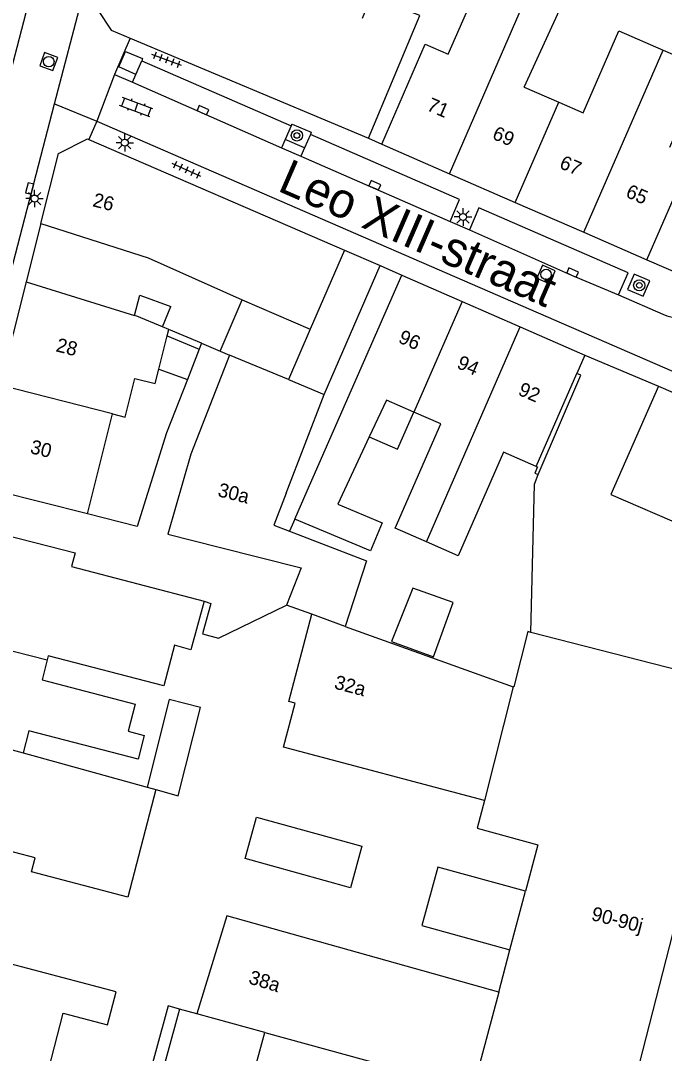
# Model space of a CAD drawing. Extents: x 132998 to 136004, y 396998 to 398512.
# Drawn here: x 133609.4 to 133655.4, y 397867.7 to 397941.4 of the extents above; entities that cross this region are included whole.
import ezdxf

# ---------------------------------------------------------------- set-up
doc = ezdxf.new("R2010")
doc.units = 0
for name, color, linetype in [('gg-afsc-erfafscheiding', 7, 'Continuous'), ('gg-afsc-hekwerk', 7, 'Continuous'), ('gg-afsc-muur', 7, 'Continuous'), ('gg-anno-huisnummerreeks BGT', 7, 'Continuous'), ('gg-anno-openbare ruimte label', 7, 'Continuous'), ('gg-bbg-bijgebouw', 7, 'Continuous'), ('gg-bbg-gedigitaliseerde bebouwing', 7, 'Continuous'), ('gg-bbg-gedigitaliseerde bijgebouw', 7, 'Continuous'), ('gg-bbg-hoofdgebouw', 7, 'Continuous'), ('gg-bbg-luifel en loopbrug', 7, 'Continuous'), ('gg-bbg-tussenscheiding', 7, 'Continuous'), ('gg-knt-verharding', 7, 'Continuous'), ('gg-knt-verharding nz', 7, 'Continuous'), ('gt-grn-weggrens', 7, 'Continuous'), ('gt-symb-boom', 7, 'Continuous'), ('gt-symb-klinker verharding', 7, 'Continuous'), ('gt-symb-kolk', 7, 'Continuous'), ('gt-symb-lichtmast', 7, 'Continuous'), ('gt-symb-rioolschacht', 7, 'Continuous'), ('gt-symb-tegel verharding', 7, 'Continuous')]:
    doc.layers.add(name, color=color, linetype=linetype)

# ---------------------------------------------------------------- blocks, each defined once
blk = doc.blocks.new('gt0-BOOM')
at = {"layer": 'gt-symb-boom'}
for radius in [0.4, 0.2]:
    blk.add_circle((0, 0), radius, dxfattribs=at)
blk = doc.blocks.new('gt0-KOLK')
at = {"layer": 'gt-symb-kolk'}
blk.add_lwpolyline([(0, 0), (0.375, 0), (0.375, 0.4), (-0.375, 0.4), (-0.375, 0), (0, 0)], dxfattribs=at)
blk = doc.blocks.new('gt0-RS')
at = {"layer": 'gt-symb-rioolschacht'}
blk.add_lwpolyline([(-0.5, -0.5), (0.5, -0.5), (0.5, 0.5), (-0.5, 0.5)], close=True, dxfattribs=at)
blk.add_circle((0, 0), 0.375, dxfattribs=at)
blk = doc.blocks.new('gt0-LMAST')
at = {"layer": 'gt-symb-lichtmast'}
for p, q in [((-0.182, 0.173), (-0.447, 0.438)), ((-0.005, 0.246), (-0.005, 0.621)), ((0.172, 0.173), (0.437, 0.438)), ((-0.255, -0.004), (-0.63, -0.004)), ((-0.182, -0.181), (-0.447, -0.446)), ((-0.005, -0.254), (-0.005, -0.629)), ((0.437, -0.446), (0.172, -0.181)), ((0.245, -0.004), (0.62, -0.004))]:
    blk.add_line(p, q, dxfattribs=at)
blk.add_circle((-0.005, -0.004), 0.25, dxfattribs=at)
blk = doc.blocks.new('gt0-KL1')
at = {"layer": 'gt-symb-klinker verharding'}
for p, q in [((-1.15, 0.3), (1.15, 0.3)), ((-1, -0.3), (-1, 0.3)), ((-0.5, 0.3), (-0.5, 0.45)), ((0, -0.3), (0, 0.3)), ((0.5, 0.3), (0.5, 0.45)), ((1, -0.3), (1, 0.3)), ((-1.15, -0.3), (1.15, -0.3)), ((-0.5, -0.45), (-0.5, -0.3)), ((0.5, -0.45), (0.5, -0.3))]:
    blk.add_line(p, q, dxfattribs=at)
blk = doc.blocks.new('gt0-TEG1')
at = {"layer": 'gt-symb-tegel verharding'}
for p, q in [((-1.125, 0), (1.125, 0)), ((-0.9, -0.25), (-0.9, 0.25)), ((-0.45, -0.25), (-0.45, 0.25)), ((0, -0.25), (0, 0.25)), ((0.45, -0.25), (0.45, 0.25)), ((0.9, -0.25), (0.9, 0.25))]:
    blk.add_line(p, q, dxfattribs=at)

msp = doc.modelspace()

# ---------------------------------------------------------------- linework, layer by layer
at = {"layer": 'gg-afsc-erfafscheiding'}
for p, q in [((133622.354, 397918.414), (133622.191, 397917.995)), ((133623.686, 397917.857), (133624.365, 397917.573)), ((133629.024, 397905.871), (133628.642, 397905))]:
    msp.add_line(p, q, dxfattribs=at)
for points in [[(133621.345, 397915.826), (133619.858, 397912.009), (133617.771, 397905.345), (133614.203, 397906.24)], [(133622.546, 397900.013), (133623.026, 397899.834), (133622.437, 397897.675), (133623.571, 397897.361), (133628.432, 397899.721)], [(133620.775, 397870.887), (133619.963, 397871.138), (133616.361, 397857.914), (133609.664, 397859.687)]]:
    msp.add_lwpolyline(points, dxfattribs=at)
at = {"layer": 'gg-afsc-hekwerk'}
msp.add_line((133649.72, 397917.56), (133654.98, 397915.36), dxfattribs=at)
at = {"layer": 'gg-afsc-muur'}
for points in [[(133646.38, 397909.052), (133649.442, 397916.135), (133649.152, 397916.259)], [(133646.253, 397909.622), (133646.34, 397909.584), (133646.155, 397909.147), (133646.38, 397909.052)], [(133645.874, 397897.783), (133646.13, 397908.348), (133646.38, 397909.052)]]:
    msp.add_lwpolyline(points, dxfattribs=at)
at = {"layer": 'gg-bbg-bijgebouw'}
for p, q in [((133610.883, 397926.954), (133609.828, 397922.788)), ((133632.553, 397925.06), (133635.12, 397923.95))]:
    msp.add_line(p, q, dxfattribs=at)
at = {"layer": 'gg-bbg-gedigitaliseerde bebouwing'}
for p, q in [((133645.392, 397936.687), (133647.869, 397935.612)), ((133625.253, 397921.522), (133630.119, 397919.412)), ((133619.901, 397918.952), (133620.012, 397919.394)), ((133619.3, 397916.559), (133619.901, 397918.952)), ((133628.569, 397915.816), (133624.365, 397917.573)), ((133646.253, 397909.622), (133649.152, 397916.259)), ((133628.397, 397907.719), (133631.119, 397914.75)), ((133614.203, 397906.24), (133615.993, 397913.379)), ((133634.322, 397911.728), (133632.078, 397906.932)), ((133613.077, 397902.474), (133622.546, 397900.013)), ((133630.241, 397899.069), (133628.432, 397899.721)), ((133632.623, 397898.212), (133644.614, 397893.896)), ((133609.613, 397889.177), (133618.479, 397886.737)), ((133618.479, 397886.737), (133619.094, 397886.568)), ((133643.574, 397872.118), (133644.379, 397875.127)), ((133626.867, 397869.227), (133641.72, 397865.179))]:
    msp.add_line(p, q, dxfattribs=at)
for points in [[(133645.392, 397936.687), (133649.627, 397945.931), (133647.227, 397946.976)], [(133639.975, 397939.042), (133642.837, 397945.615), (133643.665, 397945.255)], [(133634.27, 397933.04), (133637.934, 397941.791), (133634.462, 397943.168), (133633.837, 397941.591)], [(133647.869, 397935.612), (133649.608, 397934.857), (133652.148, 397940.71), (133655.318, 397939.334)], [(133635.22, 397932.62), (133638.327, 397939.76), (133639.975, 397939.042)], [(133655.318, 397939.334), (133658.235, 397938.068), (133655.77, 397932.389)], [(133629.024, 397905.871), (133629.906, 397907.881), (133636.66, 397923.27)], [(133619.559, 397919.583), (133617.741, 397920.343), (133617.582, 397920.392)], [(133624.365, 397917.573), (133621.595, 397910.505), (133619.939, 397904.784), (133623.623, 397903.856)], [(133615.993, 397913.379), (133616.91, 397913.145), (133617.603, 397915.906), (133619.045, 397915.544), (133619.3, 397916.559)], [(133637.506, 397913.505), (133635.553, 397914.359), (133634.322, 397911.728)], [(133638.409, 397904.237), (133636.192, 397905.206), (133639.449, 397912.656), (133637.506, 397913.505)], [(133646.253, 397909.622), (133643.917, 397910.643), (133640.682, 397903.243), (133638.409, 397904.237)], [(133628.397, 397907.719), (133627.513, 397905.437), (133628.642, 397905)], [(133632.078, 397906.932), (133635.265, 397905.595), (133634.429, 397903.603), (133629.024, 397905.871)], [(133628.642, 397905), (133634.124, 397902.876), (133632.623, 397898.212)], [(133623.623, 397903.856), (133629.463, 397902.385), (133628.432, 397899.721)], [(133622.546, 397900.013), (133621.582, 397896.541), (133620.426, 397896.862)], [(133642.553, 397885.782), (133628.212, 397889.589), (133629.043, 397892.72), (133628.588, 397892.841), (133630.241, 397899.069)], [(133645.663, 397897.838), (133644.644, 397893.885), (133644.614, 397893.896)], [(133620.426, 397896.862), (133619.671, 397893.962), (133611.417, 397896.11), (133611.343, 397895.828)], [(133611.343, 397895.828), (133610.969, 397894.389), (133617.614, 397892.66), (133617.11, 397890.724), (133618.272, 397890.422), (133617.831, 397888.729), (133610.025, 397890.759), (133609.613, 397889.177)], [(133619.094, 397886.568), (133617.097, 397878.893), (133610.213, 397880.684), (133610.476, 397881.693), (133607.56, 397882.449)], [(133642.553, 397885.782), (133642.044, 397883.807), (133646.379, 397882.611), (133645.496, 397879.306)], [(133643.574, 397872.118), (133624.173, 397877.563), (133622.016, 397870.549)], [(133613.879, 397862.863), (133614.023, 397863.421), (133610.828, 397864.244), (133612.466, 397870.606), (133615.652, 397869.786), (133616.253, 397872.119), (133598.59, 397876.79)]]:
    msp.add_lwpolyline(points, dxfattribs=at)
at = {"layer": 'gg-bbg-gedigitaliseerde bijgebouw'}
for p, q in [((133631.119, 397914.75), (133635.12, 397923.95)), ((133623.686, 397917.857), (133625.253, 397921.522)), ((133619.559, 397919.583), (133620.176, 397921.028)), ((133622.354, 397918.414), (133620.012, 397919.394)), ((133630.119, 397919.412), (133628.569, 397915.816)), ((133622.354, 397918.414), (133623.686, 397917.857)), ((133622.016, 397870.549), (133620.775, 397870.887))]:
    msp.add_line(p, q, dxfattribs=at)
for points in [[(133617.582, 397920.392), (133617.948, 397921.838), (133620.176, 397921.028)], [(133637.448, 397900.937), (133635.931, 397897.128), (133638.928, 397896.047), (133640.319, 397899.902), (133637.448, 397900.937)], [(133625.47, 397881.633), (133626.283, 397884.591), (133633.81, 397882.52), (133632.996, 397879.563), (133625.47, 397881.633)], [(133645.496, 397879.306), (133639.237, 397881.028), (133638.091, 397876.859), (133644.379, 397875.127)], [(133620.775, 397870.887), (133618.005, 397860.719), (133624.098, 397859.059), (133626.867, 397869.227)]]:
    msp.add_lwpolyline(points, dxfattribs=at)
at = {"layer": 'gg-bbg-hoofdgebouw'}
for p, q in [((133617.261, 397940.192), (133634.27, 397933.04)), ((133614.31, 397932.951), (133632.553, 397925.06)), ((133635.22, 397932.62), (133640.06, 397930.513)), ((133640.06, 397930.513), (133644.759, 397928.467)), ((133644.759, 397928.467), (133649.658, 397926.334)), ((133649.658, 397926.334), (133654.153, 397924.377)), ((133654.153, 397924.377), (133658.51, 397922.48)), ((133636.66, 397923.27), (133640.954, 397921.393)), ((133609.828, 397922.788), (133607.964, 397915.424)), ((133640.954, 397921.393), (133645.114, 397919.574)), ((133645.114, 397919.574), (133649.72, 397917.56)), ((133649.72, 397917.56), (133649.152, 397916.259)), ((133654.98, 397915.36), (133666.672, 397910.299)), ((133614.203, 397906.24), (133606.15, 397908.26)), ((133645.874, 397897.783), (133645.663, 397897.838))]:
    msp.add_line(p, q, dxfattribs=at)
for points in [[(133615.18, 397945.542), (133614.94, 397942.24), (133615.91, 397940.76), (133617.261, 397940.192)], [(133610.883, 397926.954), (133612.15, 397931.96), (133614.22, 397932.99), (133614.31, 397932.951)], [(133654.98, 397915.36), (133651.582, 397907.615), (133662.39, 397902.955)], [(133605.41, 397905.47), (133613.327, 397903.453), (133613.077, 397902.474)], [(133656.898, 397860.803), (133655.779, 397861.086), (133654.993, 397857.74), (133651.477, 397858.645), (133660.53, 397893.898), (133660.426, 397893.929), (133660.451, 397894.026), (133645.874, 397897.783)]]:
    msp.add_lwpolyline(points, dxfattribs=at)
at = {"layer": 'gg-bbg-luifel en loopbrug'}
for p, q in [((133619.901, 397918.952), (133622.191, 397917.995)), ((133622.191, 397917.995), (133621.345, 397915.826)), ((133619.3, 397916.559), (133621.345, 397915.826))]:
    msp.add_line(p, q, dxfattribs=at)
for points in [[(133634.322, 397911.728), (133636.343, 397910.845), (133637.506, 397913.505)], [(133619.094, 397886.568), (133620.697, 397886.127), (133622.287, 397892.43), (133620.057, 397892.992), (133618.479, 397886.737)]]:
    msp.add_lwpolyline(points, dxfattribs=at)
at = {"layer": 'gg-bbg-tussenscheiding'}
for p, q in [((133640.06, 397930.513), (133645.521, 397943.057)), ((133649.658, 397926.334), (133655.318, 397939.334)), ((133644.759, 397928.467), (133647.869, 397935.612)), ((133654.153, 397924.377), (133657.232, 397931.449)), ((133632.553, 397925.06), (133630.119, 397919.412)), ((133609.828, 397922.788), (133617.582, 397920.392)), ((133640.954, 397921.393), (133637.506, 397913.505)), ((133620.012, 397919.394), (133619.559, 397919.583)), ((133638.409, 397904.237), (133645.114, 397919.574)), ((133628.569, 397915.816), (133631.119, 397914.75)), ((133615.993, 397913.379), (133607.964, 397915.424)), ((133632.623, 397898.212), (133630.241, 397899.069)), ((133603.422, 397897.828), (133611.343, 397895.828)), ((133644.614, 397893.896), (133642.553, 397885.782)), ((133601.735, 397891.343), (133609.613, 397889.177)), ((133644.379, 397875.127), (133645.496, 397879.306)), ((133643.574, 397872.118), (133641.72, 397865.179)), ((133626.867, 397869.227), (133622.016, 397870.549))]:
    msp.add_line(p, q, dxfattribs=at)
msp.add_lwpolyline([(133610.883, 397926.954), (133618.535, 397924.516), (133625.253, 397921.522)], dxfattribs=at)
at = {"layer": 'gg-knt-verharding'}
for p, q in [((133617.261, 397940.192), (133616.135, 397937.59)), ((133617.673, 397937.594), (133618.101, 397938.57)), ((133618.101, 397938.57), (133628.755, 397933.921)), ((133616.135, 397937.59), (133617.428, 397937.034)), ((133617.428, 397937.034), (133617.673, 397937.594)), ((133614.874, 397934.262), (133614.31, 397932.951)), ((133614.874, 397934.262), (133704.097, 397895.507)), ((133628.755, 397933.921), (133628.331, 397932.961)), ((133630.132, 397933.315), (133629.716, 397932.357)), ((133628.331, 397932.961), (133628.066, 397932.362)), ((133629.716, 397932.357), (133628.331, 397932.961)), ((133634.27, 397933.04), (133635.22, 397932.62)), ((133628.066, 397932.362), (133629.453, 397931.752)), ((133629.716, 397932.357), (133629.453, 397931.752)), ((133640.102, 397927.103), (133641.495, 397926.501)), ((133635.12, 397923.95), (133636.66, 397923.27)), ((133652.125, 397921.873), (133655.298, 397920.494))]:
    msp.add_line(p, q, dxfattribs=at)
for points in [[(133611.866, 397935.493), (133613.875, 397943.22), (133618.023, 398000)], [(133565.5, 397779.742), (133577.243, 397816.67), (133610.301, 397943.866), (133613.733, 397990.772)], [(133617.673, 397937.594), (133616.45, 397938.147), (133616.924, 397939.238), (133618.14, 397938.724), (133618.101, 397938.57)], [(133571.202, 397785.807), (133580.793, 397815.951), (133611.866, 397935.493)], [(133628.755, 397933.921), (133628.839, 397934.057), (133630.178, 397933.475), (133630.132, 397933.315)], [(133640.102, 397927.103), (133640.781, 397928.675), (133630.132, 397933.315)], [(133652.125, 397921.873), (133652.806, 397923.431), (133642.164, 397928.074), (133641.495, 397926.501)], [(133654.357, 397922.871), (133653.255, 397923.345), (133652.769, 397922.256), (133653.889, 397921.771), (133654.357, 397922.871)]]:
    msp.add_lwpolyline(points, dxfattribs=at)
msp.add_arc((133656.592, 397923.334), 3.121, 245.50088, 331.7088, dxfattribs=at)
at = {"layer": 'gg-knt-verharding nz'}
for p, q in [((133617.428, 397937.034), (133628.066, 397932.362)), ((133629.453, 397931.752), (133640.102, 397927.103))]:
    msp.add_line(p, q, dxfattribs=at)
msp.add_lwpolyline([(133641.495, 397926.501), (133648.77, 397923.282), (133652.125, 397921.873)], dxfattribs=at)
at = {"layer": 'gt-grn-weggrens'}
for p in [(133616.135, 397937.59), (133611.866, 397935.493)]:
    msp.add_line(p, (133614.874, 397934.262), dxfattribs=at)

# ---------------------------------------------------------------- block references
at = {"layer": 'gt-symb-boom'}
for p in [(133629.163, 397933.241), (133653.609, 397922.546)]:
    msp.add_blockref('gt0-BOOM', p, dxfattribs=at)
at = {"layer": 'gt-symb-klinker verharding', "rotation": 159.39030706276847}
msp.add_blockref('gt0-KL1', (133617.689, 397935.26), dxfattribs=at)
at = {"layer": 'gt-symb-kolk'}
for p, rotation in [((133622.377, 397934.861), -23.694971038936), ((133610.278, 397929.406), 75.40804379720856), ((133634.647, 397929.508), -23.386642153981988), ((133648.769, 397923.282), -23.89847786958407)]:
    msp.add_blockref('gt0-KOLK', p, dxfattribs=dict(at, rotation=rotation))
at = {"layer": 'gt-symb-lichtmast'}
for p in [(133616.883, 397932.728), (133610.438, 397928.743), (133641.033, 397927.431)]:
    msp.add_blockref('gt0-LMAST', p, dxfattribs=at)
at = {"layer": 'gt-symb-rioolschacht'}
for p, rotation in [((133611.451, 397938.51), -109.93904791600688), ((133646.954, 397923.32), 156.74124066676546)]:
    msp.add_blockref('gt0-RS', p, dxfattribs=dict(at, rotation=rotation))
at = {"layer": 'gt-symb-tegel verharding'}
for p, rotation in [((133619.863, 397938.624), 159.2092747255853), ((133621.284, 397930.776), 155.7931560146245)]:
    msp.add_blockref('gt0-TEG1', p, dxfattribs=dict(at, rotation=rotation))

# ---------------------------------------------------------------- texts
at = {"layer": 'gg-anno-huisnummerreeks BGT'}
for s, rotation, p in [('71', 336.5, (133638.373, 397935.065)), ('69', 336.5, (133643.045, 397933.031)), ('67', 336.5, (133647.84, 397930.943)), ('65', 336.5, (133652.574, 397928.882)), ('26', 345.8, (133614.522, 397928.198)), ('96', 336.4, (133636.341, 397918.498)), ('28', 345.8, (133611.902, 397917.847)), ('94', 336.4, (133640.518, 397916.672)), ('92', 336.4, (133644.888, 397914.761)), ('30', 345.8, (133610.063, 397910.583)), ('30a', 345.9, (133623.458, 397907.506)), ('32a', 345.1, (133631.772, 397893.786)), ('90-90j', 345.6, (133650.124, 397877.265)), ('38a', 342.9, (133625.657, 397872.745))]:
    msp.add_text(s, height=1, rotation=rotation, dxfattribs=at).set_placement(p)
at = {"layer": 'gg-anno-openbare ruimte label'}
msp.add_text('Leo XIII-straat', height=2.5, rotation=336.5, dxfattribs=at).set_placement((133627.699, 397929.323))

doc.saveas('drawing.dxf')
